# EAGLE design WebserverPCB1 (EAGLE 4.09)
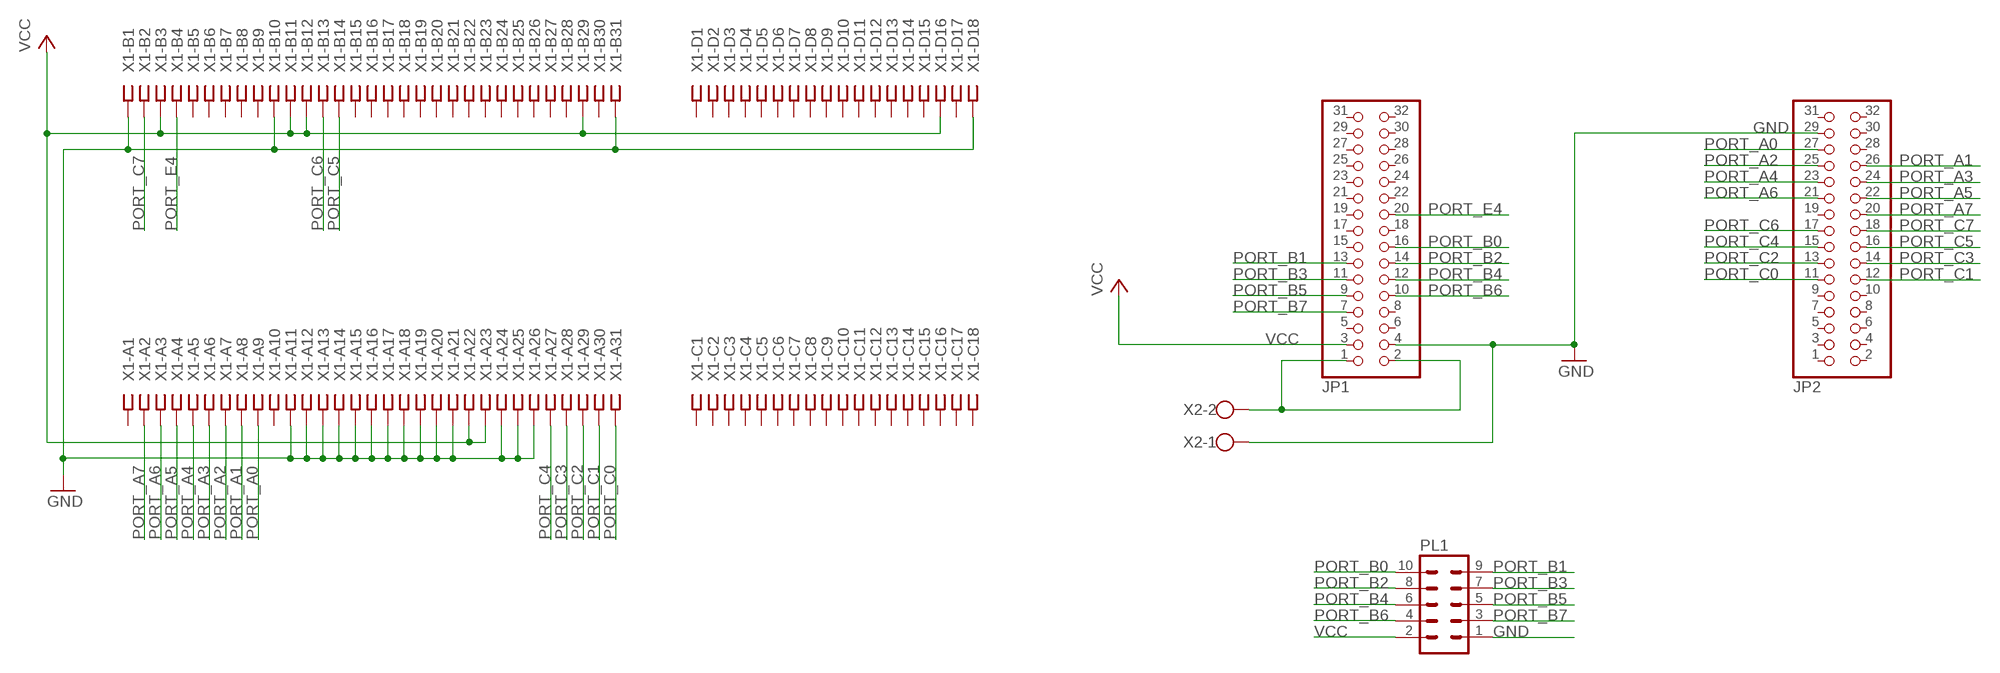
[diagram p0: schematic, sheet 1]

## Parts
JP1  PINHD-2X16  [2X16]
JP2  PINHD-2X16  [2X16]
PL1  10V  [10V]
X1  ISA-SLOT  [ISA-16]
X2  W237-102  [W237-102]

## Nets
GND: JP1.4 JP2.29 PL1.1 X1.A11 X1.A12 X1.A13 X1.A14 X1.A15 X1.A16 X1.A17 X1.A18 X1.A19 X1.A20 X1.A21 X1.A24 X1.A25 X1.A26 X1.B1 X1.B10 X1.B31 X1.D18 X2.1
N$1: JP1.1 JP1.2 X2.2
PORT_A0: JP2.27 X1.A9
PORT_A1: JP2.26 X1.A8
PORT_A2: JP2.25 X1.A7
PORT_A3: JP2.24 X1.A6
PORT_A4: JP2.23 X1.A5
PORT_A5: JP2.22 X1.A4
PORT_A6: JP2.21 X1.A3
PORT_A7: JP2.20 X1.A2
PORT_B0: JP1.16 PL1.10
PORT_B1: JP1.13 PL1.9
PORT_B2: JP1.14 PL1.8
PORT_B3: JP1.11 PL1.7
PORT_B4: JP1.12 PL1.6
PORT_B5: JP1.9 PL1.5
PORT_B6: JP1.10 PL1.4
PORT_B7: JP1.7 PL1.3
PORT_C0: JP2.11 X1.A31
PORT_C1: JP2.12 X1.A30
PORT_C2: JP2.13 X1.A29
PORT_C3: JP2.14 X1.A28
PORT_C4: JP2.15 X1.A27
PORT_C5: JP2.16 X1.B14
PORT_C6: JP2.17 X1.B13
PORT_C7: JP2.18 X1.B2
PORT_E4: JP1.20 X1.B4
VCC: JP1.3 PL1.2 X1.A22 X1.A23 X1.B3 X1.B11 X1.B12 X1.B29 X1.D16
Unconnected: JP1.5 JP1.6 JP1.8 JP1.15 JP1.17 JP1.18 JP1.19 JP1.21 JP1.22 JP1.23 JP1.24 JP1.25 JP1.26 JP1.27 JP1.28 JP1.29 JP1.30 JP1.31 JP1.32 JP2.1 JP2.2 JP2.3 JP2.4 JP2.5 JP2.6 JP2.7 JP2.8 JP2.9 JP2.10 JP2.19 JP2.28 JP2.30 JP2.31 JP2.32 X1.A1 X1.A10 X1.B5 X1.B6 X1.B7 X1.B8 X1.B9 X1.B15 X1.B16 X1.B17 X1.B18 X1.B19 X1.B20 X1.B21 X1.B22 X1.B23 X1.B24 X1.B25 X1.B26 X1.B27 X1.B28 X1.B30 X1.C1 X1.C2 X1.C3 X1.C4 X1.C5 X1.C6 X1.C7 X1.C8 X1.C9 X1.C10 X1.C11 X1.C12 X1.C13 X1.C14 X1.C15 X1.C16 X1.C17 X1.C18 X1.D1 X1.D2 X1.D3 X1.D4 X1.D5 X1.D6 X1.D7 X1.D8 X1.D9 X1.D10 X1.D11 X1.D12 X1.D13 X1.D14 X1.D15 X1.D17

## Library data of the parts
JP1 JP2 = pinhead:PINHD-2X16: PIN HEADER
PL1 = con-harting-v:10V: CONNECTOR
X1 = con-pc:ISA-SLOT: ISA SLOT
X2 = con-wago-500:W237-102: WAGO SCREW CLAMP

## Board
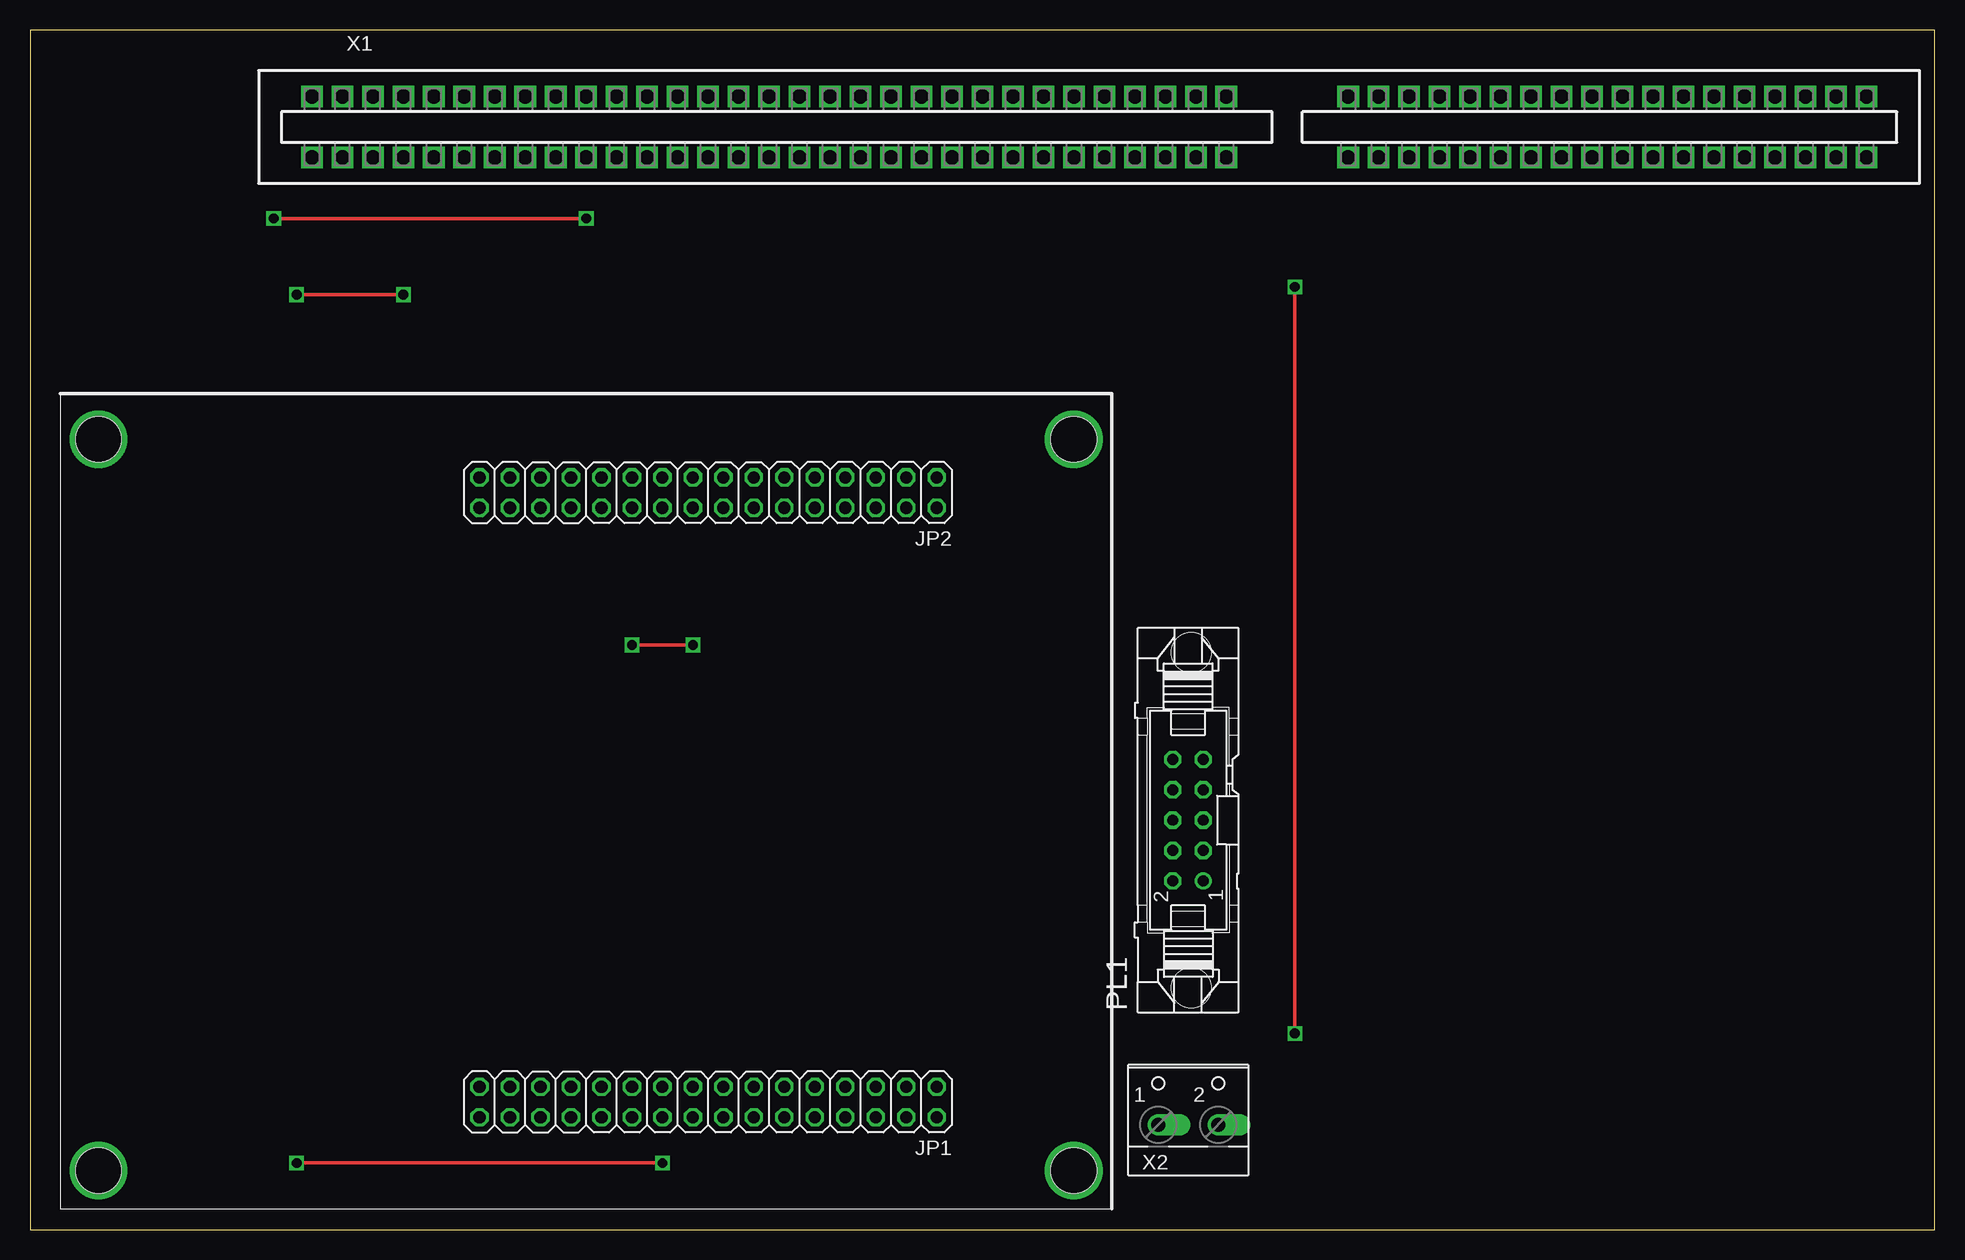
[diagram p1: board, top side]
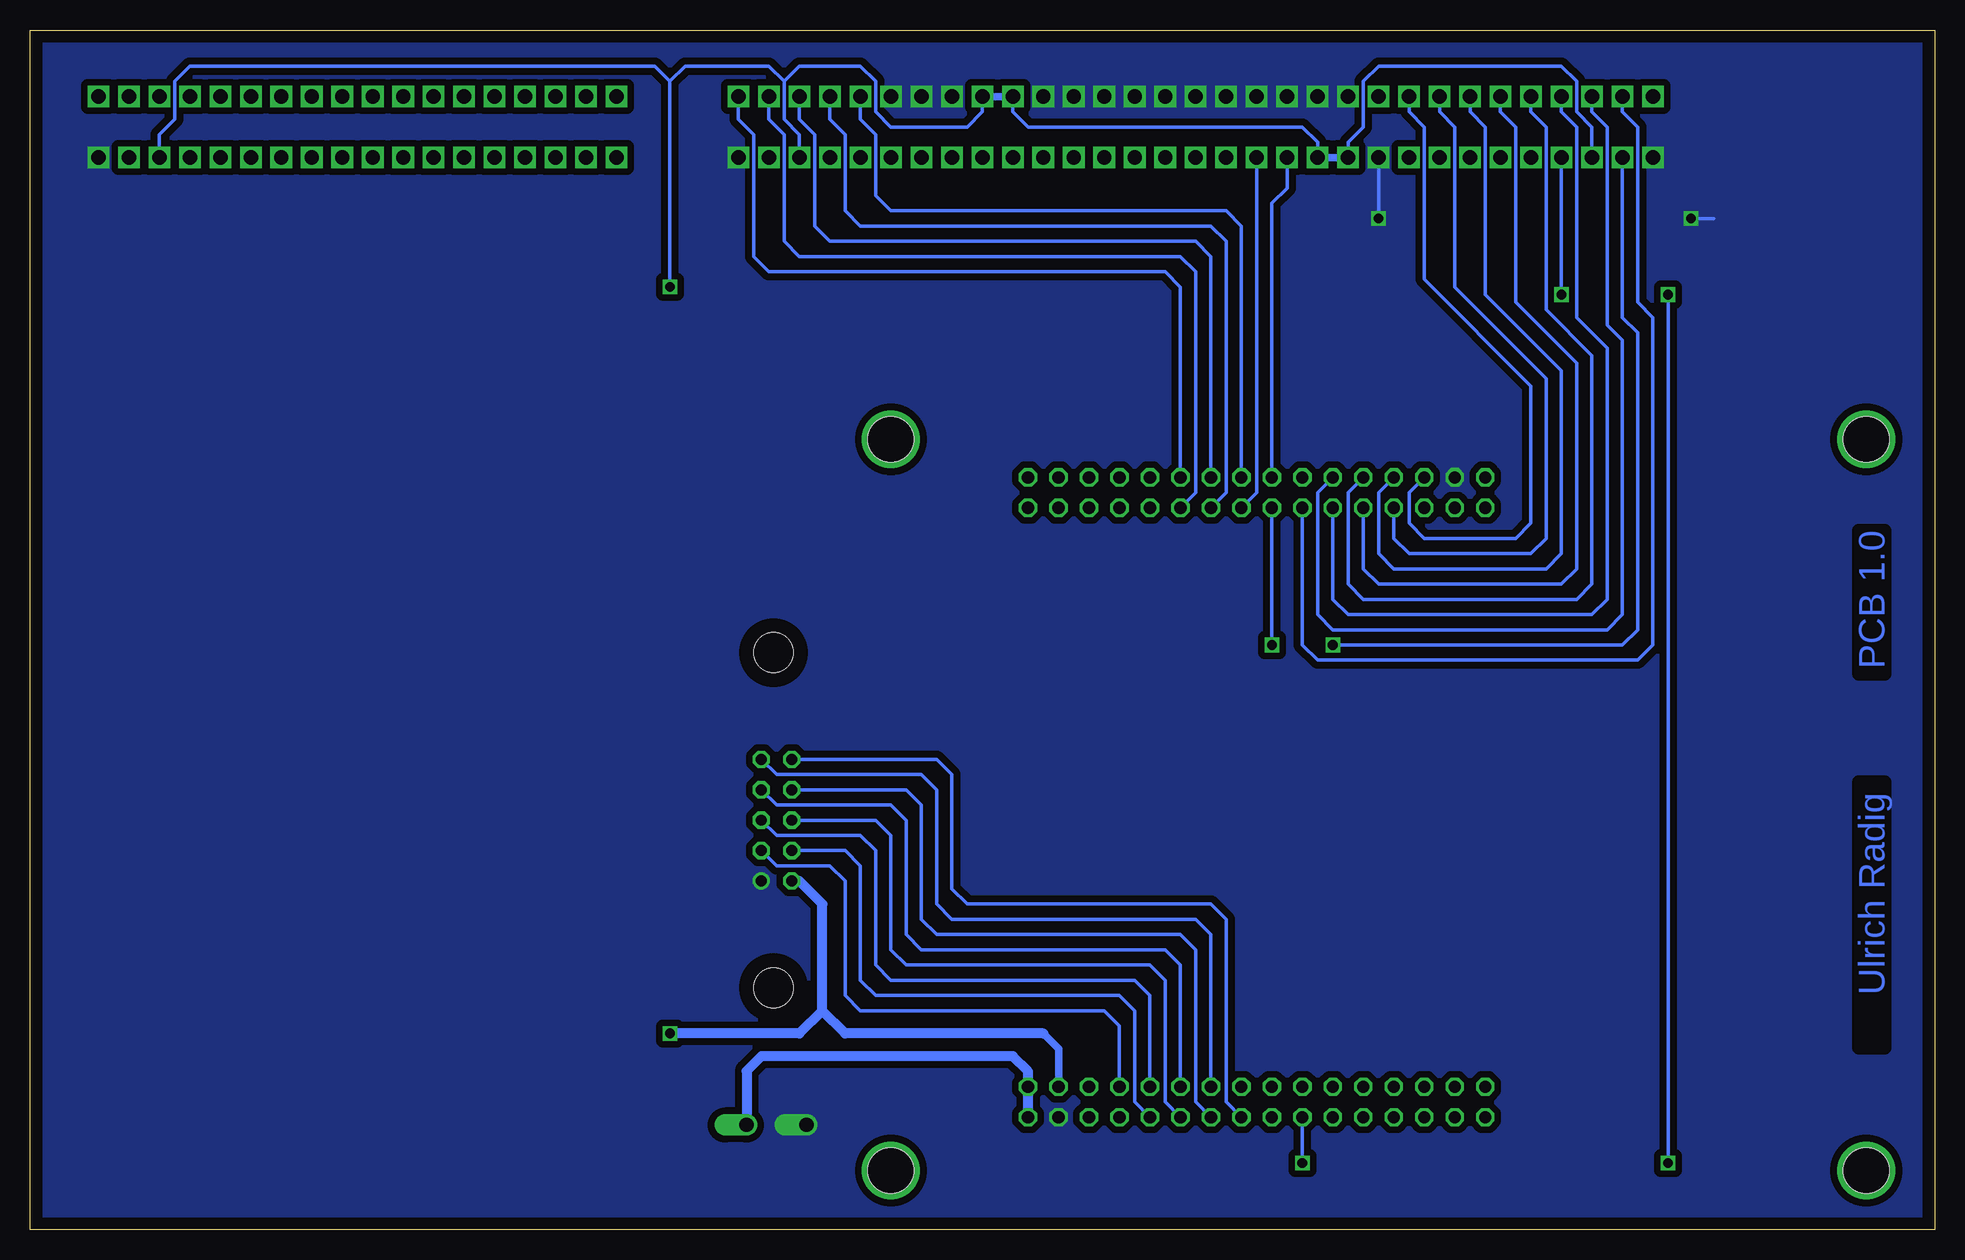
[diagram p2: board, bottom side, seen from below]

Size 158.73 x 100 mm. Coordinates in mm from the lower left corner, seen from the top.
Outline: 0,0 158.73,0 158.73,100 0,100 0,0
Copper layers used: Top, Bottom
Holes 3.81 mm at 86.99,4.92 86.99,65.88 5.71,65.88 5.71,4.92

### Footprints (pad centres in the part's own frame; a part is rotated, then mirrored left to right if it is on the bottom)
2X16 = drill 1.016 octagon: 1 -19.05,-1.27; 2 -19.05,1.27; 3 -16.51,-1.27; 4 -16.51,1.27; 5 -13.97,-1.27; 6 -13.97,1.27; 7 -11.43,-1.27; 8 -11.43,1.27; 9 -8.89,-1.27; 10 -8.89,1.27; 11 -6.35,-1.27; 12 -6.35,1.27; 13 -3.81,-1.27; 14 -3.81,1.27; 15 -1.27,-1.27; 16 -1.27,1.27; 17 1.27,-1.27; 18 1.27,1.27; 19 3.81,-1.27; 20 3.81,1.27; 21 6.35,-1.27; 22 6.35,1.27; 23 8.89,-1.27; 24 8.89,1.27; 25 11.43,-1.27; 26 11.43,1.27; 27 13.97,-1.27; 28 13.97,1.27; 29 16.51,-1.27; 30 16.51,1.27; 31 19.05,-1.27; 32 19.05,1.27
10V = drill 0.914 round: 1 -5.08,-1.27 | drill 0.914 octagon: 2 -5.08,1.27; 3 -2.54,-1.27; 4 -2.54,1.27; 5 0,-1.27; 6 0,1.27; 7 2.54,-1.27; 8 2.54,1.27; 9 5.08,-1.27; 10 5.08,1.27 | hole 3.302: 13.97,-0.254; -13.97,-0.254
ISA-16 = drill 1.2 pad 1.778 square: A1 81.28,-2.54; A2 78.74,-2.54; A3 76.2,-2.54; A4 73.66,-2.54; A5 71.12,-2.54; A6 68.58,-2.54; A7 66.04,-2.54; A8 63.5,-2.54; A9 60.96,-2.54; A10 58.42,-2.54; A11 55.88,-2.54; A12 53.34,-2.54; A13 50.8,-2.54; A14 48.26,-2.54; A15 45.72,-2.54; A16 43.18,-2.54; A17 40.64,-2.54; A18 38.1,-2.54; A19 35.56,-2.54; A20 33.02,-2.54; A21 30.48,-2.54; A22 27.94,-2.54; A23 25.4,-2.54; A24 22.86,-2.54; A25 20.32,-2.54; A26 17.78,-2.54; A27 15.24,-2.54; A28 12.7,-2.54; A29 10.16,-2.54; A30 7.62,-2.54; A31 5.08,-2.54; B1 81.28,2.54; B2 78.74,2.54; B3 76.2,2.54; B4 73.66,2.54; B5 71.12,2.54; B6 68.58,2.54; B7 66.04,2.54; B8 63.5,2.54; B9 60.96,2.54; B10 58.42,2.54; B11 55.88,2.54; B12 53.34,2.54; B13 50.8,2.54; B14 48.26,2.54; B15 45.72,2.54; B16 43.18,2.54; B17 40.64,2.54; B18 38.1,2.54; B19 35.56,2.54; B20 33.02,2.54; B21 30.48,2.54; B22 27.94,2.54; B23 25.4,2.54; B24 22.86,2.54; B25 20.32,2.54; B26 17.78,2.54; B27 15.24,2.54; B28 12.7,2.54; B29 10.16,2.54; B30 7.62,2.54; B31 5.08,2.54; C1 -5.08,-2.54; C2 -7.62,-2.54; C3 -10.16,-2.54; C4 -12.7,-2.54; C5 -15.24,-2.54; C6 -17.78,-2.54; C7 -20.32,-2.54; C8 -22.86,-2.54; C9 -25.4,-2.54; C10 -27.94,-2.54; C11 -30.48,-2.54; C12 -33.02,-2.54; C13 -35.56,-2.54; C14 -38.1,-2.54; C15 -40.64,-2.54; C16 -43.18,-2.54; C17 -45.72,-2.54; C18 -48.26,-2.54; D1 -5.08,2.54; D2 -7.62,2.54; D3 -10.16,2.54; D4 -12.7,2.54; D5 -15.24,2.54; D6 -17.78,2.54; D7 -20.32,2.54; D8 -22.86,2.54; D9 -25.4,2.54; D10 -27.94,2.54; D11 -30.48,2.54; D12 -33.02,2.54; D13 -35.56,2.54; D14 -38.1,2.54; D15 -40.64,2.54; D16 -43.18,2.54; D17 -45.72,2.54; D18 -48.26,2.54
W237-102 = drill 1.194 offset: 1 -2.5,-1.27; 2 2.5,-1.27

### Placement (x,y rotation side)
JP1  56.51,10.63 180 top
JP2  56.51,61.43 180 top
PL1  96.52,34.12 90 top
X1  104.77,91.91 180 top
X2  96.52,10 0 top

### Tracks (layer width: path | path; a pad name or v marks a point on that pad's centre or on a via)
GND  (via drill 0.81)
  Top 0.305: v20.31,84.29 v46.35,84.29
  Bottom 0.305: v46.35,84.29 X1.B10 | 18.41,84.29 v20.31,84.29
  pour Bottom (isolate 0.571, no thermals): 0.63,99.53 0.63,0.47 158.11,0.47 158.11,99.53
N$1
  Bottom 0.813: JP1.2 JP1.1 75.56,13.17 76.83,14.44 97.78,14.44 99.02,13.21 X2.2
N$5  (via drill 3.81)
  other vias: 86.99,4.92
N$6  (via drill 3.81)
  other vias: 5.71,4.92
N$7  (via drill 3.81)
  other vias: 5.71,65.88
N$8  (via drill 3.81)
  other vias: 86.99,65.88
PORT_A0
  Bottom 0.305: X1.A9 43.81,93.18 42.54,91.91 42.54,79.21 33.65,70.32 33.65,58.89 34.92,57.62 42.54,57.62 43.81,58.89 43.81,61.43 JP2.27
PORT_A1
  Bottom 0.305: X1.A8 41.27,93.18 40,91.91 40,78.57 32.38,70.95 32.38,57.62 33.65,56.35 43.81,56.35 45.08,57.62 JP2.26
PORT_A2
  Bottom 0.305: X1.A7 38.73,93.18 37.46,91.91 37.46,77.94 31.11,71.59 31.11,56.35 32.38,55.08 45.08,55.08 46.35,56.35 46.35,61.43 JP2.25
PORT_A3
  Bottom 0.305: X1.A6 36.19,93.18 34.92,91.91 34.92,77.3 29.84,72.22 29.84,55.08 31.11,53.81 46.35,53.81 47.62,55.08 JP2.24
PORT_A4
  Bottom 0.305: X1.A5 33.65,93.18 32.38,91.91 32.38,76.67 28.57,72.86 28.57,53.81 29.84,52.54 47.62,52.54 48.89,53.81 48.89,61.43 JP2.23
PORT_A5
  Bottom 0.305: X1.A4 31.11,93.18 29.84,91.91 29.84,76.03 27.3,73.49 27.3,52.54 28.57,51.27 48.89,51.27 50.16,52.54 JP2.22
PORT_A6
  Bottom 0.305: X1.A3 28.57,93.18 27.3,91.91 27.3,75.4 26.03,74.13 26.03,51.27 27.3,50 50.16,50 51.43,51.27 51.43,61.43 JP2.21
PORT_A7
  Bottom 0.305: X1.A2 26.03,93.18 24.76,91.91 24.76,77.3 23.49,76.03 23.49,48.73 24.76,47.46 51.43,47.46 52.7,48.73 JP2.20
PORT_B0
  Bottom 0.305: JP1.16 59.05,10.63 59.05,25.87 60.32,27.14 80.64,27.14 81.91,28.41 81.91,37.94 83.18,39.2 PL1.10
PORT_B1
  Bottom 0.305: JP1.13 60.32,24.6 61.59,25.87 81.91,25.87 83.18,27.14 83.18,36.66 84.45,37.94 96.52,37.94 PL1.9
PORT_B2
  Bottom 0.305: PL1.8 85.72,36.66 84.45,35.4 84.45,25.87 83.18,24.6 62.86,24.6 61.59,23.33 61.59,10.63 JP1.14
PORT_B3
  Bottom 0.305: JP1.11 62.86,22.06 64.13,23.33 84.45,23.33 85.72,24.6 85.72,34.12 86.99,35.4 96.52,35.4 PL1.7
PORT_B4
  Bottom 0.305: PL1.6 88.26,34.12 86.99,32.86 86.99,23.33 85.72,22.06 65.4,22.06 64.13,20.79 64.13,10.63 JP1.12
PORT_B5
  Bottom 0.305: JP1.9 65.4,19.52 66.67,20.79 86.99,20.79 88.26,22.06 88.26,31.59 89.53,32.86 96.52,32.86 PL1.5
PORT_B6
  Bottom 0.305: PL1.4 90.8,31.59 89.53,30.32 89.53,20.79 88.26,19.52 67.94,19.52 66.67,18.25 66.67,10.63 JP1.10
PORT_B7
  Bottom 0.305: JP1.7 67.94,16.98 69.21,18.25 89.53,18.25 90.8,19.52 90.8,29.05 92.07,30.32 | 92.07,30.32 | 92.07,30.32 96.52,30.32 PL1.3
PORT_C0
  Bottom 0.305: JP2.11 62.86,78.57 64.13,79.84 97.15,79.84 98.42,81.11 98.42,91.27 99.69,92.54 X1.A31
PORT_C1
  Bottom 0.305: JP2.12 61.59,61.43 61.59,79.84 62.86,81.11 94.61,81.11 95.88,82.38 95.88,91.27 97.15,92.54 X1.A30
PORT_C2
  Bottom 0.305: JP2.13 60.32,81.11 61.59,82.38 92.07,82.38 93.34,83.65 93.34,91.27 94.61,92.54 X1.A29
PORT_C3
  Bottom 0.305: JP2.14 59.05,61.43 59.05,82.38 60.32,83.65 89.53,83.65 90.8,84.92 90.8,91.27 92.07,92.54 X1.A28
PORT_C4
  Bottom 0.305: JP2.15 57.78,83.65 59.05,84.92 86.99,84.92 88.26,86.19 88.26,91.27 89.53,92.54 X1.A27
PORT_C5
  Bottom 0.305: JP2.16 56.51,61.43 X1.B14
PORT_C6
  Bottom 0.305: JP2.17 55.24,85.56 53.97,86.83 X1.B13
PORT_C7  (via drill 0.81)
  Top 0.305: v50.16,48.73 v55.24,48.73
  Bottom 0.305: X1.B2 26.03,76.03 24.76,74.77 24.76,50 26.03,48.73 v50.16,48.73 | v55.24,48.73 JP2.18
PORT_E4  (via drill 0.81)
  Top 0.305: v22.22,77.94 v31.11,77.94 | v22.22,5.55 v52.7,5.55
  Bottom 0.305: v31.11,77.94 X1.B4 | v22.22,5.55 v22.22,77.94 | v52.7,5.55 JP1.20
VCC  (via drill 0.81)
  Top 0.305: v105.41,16.35 v105.41,78.57
  Bottom 0.305: X1.B12 51.43,90.64 52.7,91.91 75.56,91.91 76.83,93.18 X1.A22 | X1.B3 28.57,91.91 29.84,93.18 29.84,95.72 31.11,96.99 46.35,96.99 47.62,95.72 47.62,91.91 48.89,90.64 X1.B11 | X1.A23 79.37,93.18 80.64,91.91 86.99,91.91 88.26,93.18 88.26,95.72 89.53,96.99 94.61,96.99 95.88,95.72 | X1.B29 94.61,91.27 95.88,92.54 95.88,95.72 | 95.88,95.72 97.15,96.99 104.14,96.99 105.41,95.72 | X1.D16 147.95,91.27 146.68,92.54 146.68,95.72 145.41,96.99 106.67,96.99 105.41,95.72 | v105.41,78.57 105.41,95.72
  Bottom 0.61: X1.A23 X1.A22 | X1.B12 X1.B11 | JP1.3 73.02,15.08 74.29,16.35
  Bottom 0.813: 74.29,16.35 90.8,16.35 92.7,18.25 | 92.7,18.25 94.61,16.35 v105.41,16.35 | 92.7,18.25 92.7,27.14 94.61,29.05 PL1.2

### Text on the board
Bottom: PCB 1.0 | Ulrich Radig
